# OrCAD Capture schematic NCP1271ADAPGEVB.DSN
size A
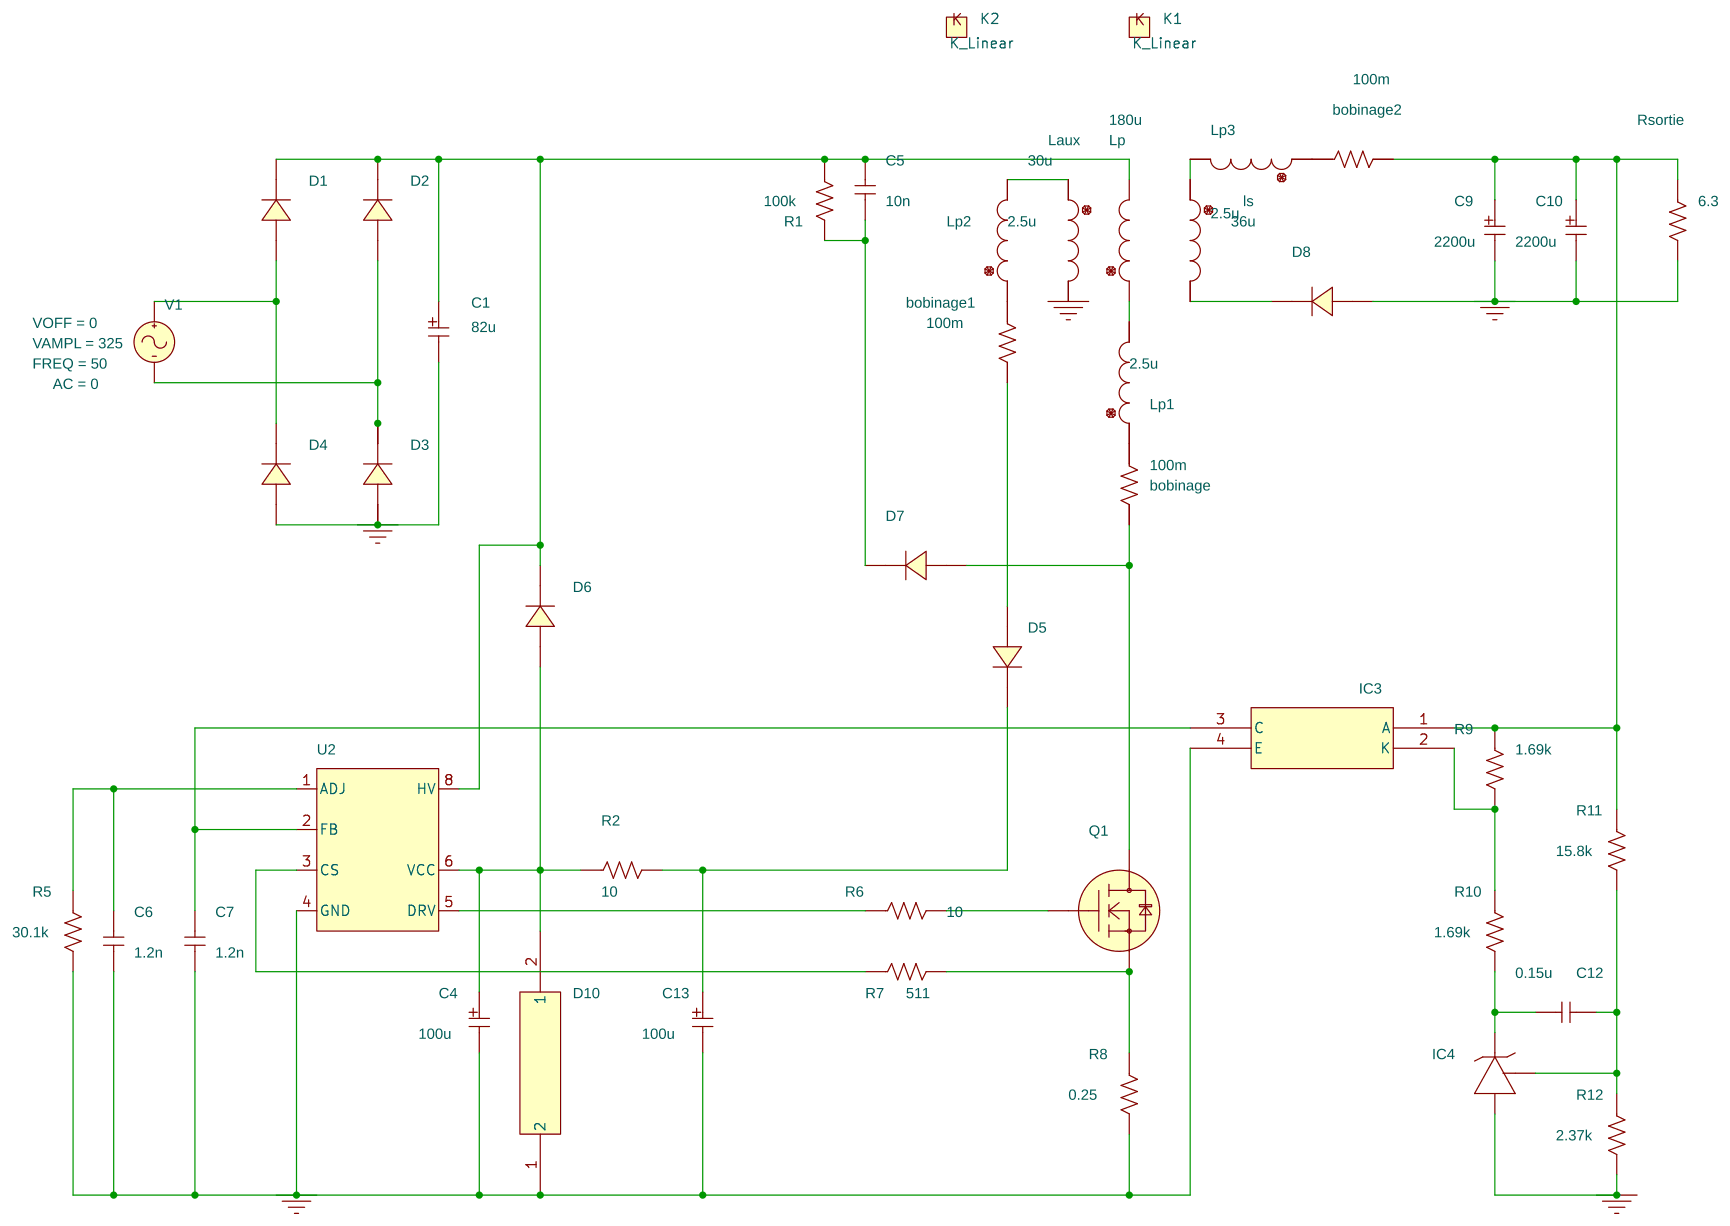
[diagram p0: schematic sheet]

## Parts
bobinage  100m  [AX/RC05]
bobinage1  100m  [AX/RC05]
bobinage2  100m  [AX/RC05]
C1  82u  [CPAX/.575x.150/.031]
C4  100u  [CPAX/.575x.150/.031]
C5  10n  [RAD/CK05]
C6  1.2n  [RAD/CK05]
C7  1.2n  [RAD/CK05]
C9  2200u  [CPAX/.575x.150/.031]
C10  2200u  [CPAX/.575x.150/.031]
C12  0.15u  [RAD/CK05]
C13  100u  [CPAX/.575x.150/.031]
D1  D1N5406RL/ON  [DO41]
D2  D1N5406RL/ON  [DO41]
D3  D1N5406RL/ON  [DO41]
D4  D1N5406RL/ON  [DO41]
D5  DMMSD4148T1/ON  [DO41]
D6  DMRA4005T3/ON  [DO41]
D7  MURS160T3G  [SMB403A]
D8  DMBR3100RL/ON  [DO41]
D10  D1N5931B/ON
IC3  VO615A/VSH
IC4  TL431/TI
K1  K_Linear
K2  K_Linear
Laux  30u  [DISC/.350x.175/LS.200x.100/.034]
Lp  180u  [DISC/.350x.175/LS.200x.100/.034]
Lp1  2.5u  [DISC/.350x.175/LS.200x.100/.034]
Lp2  2.5u  [DISC/.350x.175/LS.200x.100/.034]
Lp3  2.5u  [DISC/.350x.175/LS.200x.100/.034]
ls  36u  [DISC/.350x.175/LS.200x.100/.034]
Q1  SPP06N80C3_L1
R1  100k  [AX/RC05]
R2  10  [AX/RC05]
R5  30.1k  [AX/RC05]
R6  10  [AX/RC05]
R7  511  [AX/RC05]
R8  0.25  [AX/RC05]
R9  1.69k  [AX/RC05]
R10  1.69k  [AX/RC05]
R11  15.8k  [AX/RC05]
R12  2.37k  [AX/RC05]
Rsortie  6.3  [AX/RC05]
U2  NCP1200/ON
V1  VSIN

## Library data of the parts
bobinage bobinage1 bobinage2 R1 R2 R5-R12 Rsortie = R
C1 C4 C9 C10 C13 = C_elect
C5-C7 C12 = C
D1-D4 = D1N5406RL_ON
D5 = DMMSD4148T1_ON
D6 = DMRA4005T3_ON
D7 = MURS160T3G
D8 = DMBR3100RL_ON
D10 = D1N5931B_ON
IC3 = VO615A_VSH
IC4 = TL431_TI
K1 = K_Linear: COUPLING: 0.99; L1: Lp; L2: Ls
K2 = K_Linear: COUPLING: 0.99; L1: Lp; L2: Laux
Laux Lp Lp1-Lp3 ls = L
Q1 = SPP06N80C3_L1
U2 = NCP1200_ON_0
V1 = VSIN: AC: 0; FREQ: 50; VAMPL: 325; VOFF: 0

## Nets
0: C1.N(-) C4.N(-) C6.1 C7.1 C9.N(-) C10.N(-) C13.N(-) D3.2(A) D4.2(A) D8.2(A) D10.1(2) IC3.4(E) IC4.2(AN) Laux.2 R5.2 R8.2 R12.2 Rsortie.2 U2.4(GND)
N00390: C1.P(+) C5.2 D1.1(C) D2.1(C) D6.1(C) Lp.2 R1.1 U2.8(HV)
N00394: D2.2(A) D3.1(C) V1.2(-)
N00398: D1.2(A) D4.1(C) V1.1(+)
N00759: C6.2 R5.1 U2.1(ADJ)
N00779: C7.2 IC3.3(C) U2.2(FB)
N00923: C4.P(+) D6.2(A) D10.2(1) R2.1 U2.6(VCC)
N00975: C13.P(+) D5.1(C) R2.2
N01759: R6.1 U2.5(DRV)
N01763: Q1.3(source) R7.2 R8.1
N01783: R7.1 U2.3(CS)
N02540: bobinage.2 D7.2(A) Q1.1(drain)
N02545: C5.1 D7.1(C) R1.2
N02640: bobinage2.2 C9.P(+) C10.P(+) IC3.1(A) R9.1 R11.1 Rsortie.1
N02649: D8.1(C) ls.2
N03154: C12.1 IC4.1(REF) R11.2 R12.1
N03416: C12.2 IC4.3(CAT) R10.2
N03420: IC3.2(K) R9.2 R10.1
N09625: Q1.2(gate) R6.2
N10689: Lp3.2 ls.1
N11179: Laux.1 Lp2.2
N16659: Lp.1 Lp1.2
N17037: bobinage1.2 D5.2(A)
N19339: bobinage.1 Lp1.1
N19373: bobinage1.1 Lp2.1
N19673: bobinage2.1 Lp3.1
